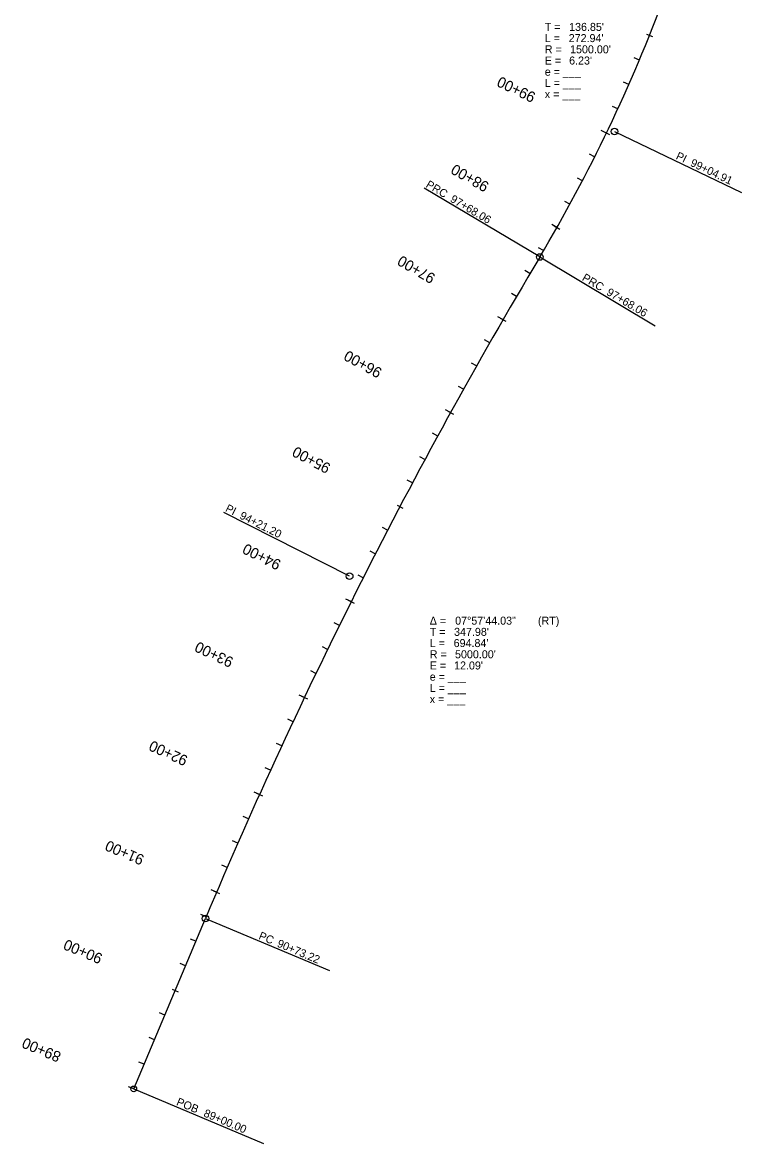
# Model space of a CAD drawing. Extents: x 14118486 to 14119897, y 8667783 to 8670021.
# Drawn here: x 14118486 to 14119160, y 8667783 to 8668833 of the extents above; entities that cross this region are included whole.
import ezdxf

# ---------------------------------------------------------------- set-up
doc = ezdxf.new("R2010")
doc.units = 0
for name, color, linetype in [('Alignment', 7, 'Continuous'), ('Draft_5', 7, 'Continuous'), ('TextAlignment', 7, 'Continuous'), ('TextAlignmentLrg', 7, 'Continuous'), ('TextAlignmentSml', 7, 'Continuous')]:
    doc.layers.add(name, color=color, linetype=linetype)

msp = doc.modelspace()

# ---------------------------------------------------------------- linework, layer by layer
at = {"layer": 'Alignment'}
msp.add_line((14118590.3, 8667833.8), (14118657.6, 8667993.5), dxfattribs=at)
for centre, radius, start, end in [((14117682.3, 8669381.1), 1500, 329.2012, 339.6267), ((14123265.6, 8666052.9), 5000, 149.2011, 157.1633)]:
    msp.add_arc(centre, radius, start, end, dxfattribs=at)
at = {"layer": 'Draft_5'}
msp.add_line((14118590.3, 8667833.8), (14118657.6, 8667993.5), dxfattribs=at)
for centre, radius, start, end in [((14117682.3, 8669381.1), 1500, 329.2012, 339.6267), ((14123265.6, 8666052.9), 5000, 149.2011, 157.1633)]:
    msp.add_arc(centre, radius, start, end, dxfattribs=at)
at = {"layer": 'TextAlignment'}
for p, q in [((14119040.9, 8668730.6), (14119159.9, 8668673.6)), ((14118970.8, 8668613.1), (14118862.6, 8668677.6)), ((14118862.6, 8668677.6), (14118862.6, 8668677.6)), ((14119159.9, 8668673.6), (14119159.9, 8668673.6)), ((14118970.8, 8668613.1), (14119079, 8668548.6)), ((14119079, 8668548.6), (14119079, 8668548.6)), ((14118792.6, 8668314.2), (14118674.8, 8668373.7)), ((14118674.8, 8668373.7), (14118674.8, 8668373.7)), ((14118657.6, 8667993.5), (14118773.7, 8667944.6)), ((14118773.7, 8667944.6), (14118773.7, 8667944.6)), ((14118590.3, 8667833.8), (14118712, 8667782.6)), ((14118712, 8667782.6), (14118712, 8667782.6))]:
    msp.add_line(p, q, dxfattribs=at)
for centre, radius in [((14119040.9, 8668730.6), 3.12), ((14118970.8, 8668613.1), 3.12), ((14118970.8, 8668613.1), 3.12), ((14118792.6, 8668314.2), 3.12), ((14118657.6, 8667993.5), 3.12), ((14118590.3, 8667833.8), 2.67)]:
    msp.add_circle(centre, radius, dxfattribs=at)
at = {"layer": 'TextAlignmentLrg'}
for p, q in [((14119070.9, 8668821.8), (14119076.5, 8668819.5)), ((14119033.3, 8668729.2), (14119028.4, 8668731.6)), ((14118986.8, 8668640.7), (14118982.1, 8668643.4)), ((14118936.3, 8668554.4), (14118931.6, 8668557.1)), ((14118887.2, 8668467.3), (14118882.4, 8668469.9)), ((14118837.1, 8668380.7), (14118842.5, 8668377.8)), ((14118794.1, 8668290.3), (14118789.2, 8668292.7)), ((14118750.3, 8668200.4), (14118745.3, 8668202.8)), ((14118708.2, 8668109.7), (14118703.3, 8668111.9)), ((14118668, 8668018.1), (14118663, 8668020.3)), ((14118626.3, 8667927.2), (14118632, 8667924.8)), ((14118590.3, 8667833.8), (14118585.3, 8667835.9))]:
    msp.add_line(p, q, dxfattribs=at)
at = {"layer": 'TextAlignmentSml'}
for p, q in [((14119070.9, 8668821.8), (14119076.5, 8668819.5)), ((14119064.2, 8668797.6), (14119059.1, 8668799.7)), ((14119054.2, 8668774.6), (14119049.3, 8668776.8)), ((14119043.9, 8668751.8), (14119039, 8668754.1)), ((14119030.5, 8668730.6), (14119036, 8668727.9)), ((14119022.2, 8668706.8), (14119017.3, 8668709.3)), ((14119010.8, 8668684.6), (14119006, 8668687.1)), ((14118999, 8668662.5), (14118994.2, 8668665.1)), ((14118984.2, 8668642.2), (14118989.5, 8668639.2)), ((14118974.3, 8668619.1), (14118969.6, 8668621.8)), ((14118961.6, 8668597.6), (14118956.9, 8668600.3)), ((14118948.9, 8668576), (14118944.2, 8668578.8)), ((14118933.7, 8668555.9), (14118939, 8668552.9)), ((14118923.9, 8668532.7), (14118919.1, 8668535.4)), ((14118911.5, 8668511), (14118906.8, 8668513.6)), ((14118899.3, 8668489.2), (14118894.5, 8668491.8)), ((14118884.5, 8668468.8), (14118889.9, 8668465.8)), ((14118875.2, 8668445.4), (14118870.4, 8668448)), ((14118863.2, 8668423.4), (14118858.4, 8668426)), ((14118851.5, 8668401.4), (14118846.6, 8668403.9)), ((14118837.1, 8668380.7), (14118842.5, 8668377.8)), ((14118828.2, 8668357.1), (14118823.3, 8668359.6)), ((14118816.7, 8668334.9), (14118811.9, 8668337.4)), ((14118805.4, 8668312.6), (14118800.5, 8668315.1)), ((14118791.4, 8668291.6), (14118796.9, 8668288.9)), ((14118783, 8668267.9), (14118778.1, 8668270.3)), ((14118772, 8668245.5), (14118767.1, 8668247.8)), ((14118761.1, 8668223), (14118756.2, 8668225.3)), ((14118747.5, 8668201.7), (14118753, 8668199.1)), ((14118739.6, 8668177.8), (14118734.7, 8668180.1)), ((14118729, 8668155.1), (14118724.1, 8668157.4)), ((14118718.6, 8668132.4), (14118713.6, 8668134.7)), ((14118705.4, 8668110.9), (14118711, 8668108.4)), ((14118698, 8668086.9), (14118693, 8668089.1)), ((14118687.9, 8668064), (14118682.9, 8668066.2)), ((14118677.9, 8668041.1), (14118672.9, 8668043.3)), ((14118665.2, 8668019.3), (14118670.8, 8668016.9)), ((14118658.2, 8667995.1), (14118653.2, 8667997.2)), ((14118648.5, 8667972.1), (14118643.5, 8667974.2)), ((14118638.8, 8667949), (14118633.8, 8667951.2)), ((14118626.3, 8667927.2), (14118632, 8667924.8)), ((14118619.4, 8667903), (14118614.4, 8667905.1)), ((14118609.7, 8667879.9), (14118604.7, 8667882)), ((14118600, 8667856.9), (14118595, 8667859)), ((14118587.5, 8667835), (14118593.1, 8667832.6))]:
    msp.add_line(p, q, dxfattribs=at)

# ---------------------------------------------------------------- texts
at = {"layer": 'TextAlignment'}
for s, p in [('T = ', (14118975.5, 8668824.9)), ("136.85'", (14118998.3, 8668824.9)), ('L = ', (14118975.5, 8668814.4)), ("272.94'", (14118997.9, 8668814.4)), ('R = ', (14118975.5, 8668803.9)), ("1500.00'", (14118999.2, 8668803.9)), ('E = ', (14118975.5, 8668793.4)), ("6.23'", (14118998.3, 8668793.4)), ('e = ___ ', (14118975.5, 8668782.9)), ('L = ___', (14118975.5, 8668772.4)), ('x = ___', (14118975.5, 8668761.9)), ('Δ = ', (14118867.7, 8668268.7)), ('07°57\'44.03"', (14118891.5, 8668268.7)), (' (RT)', (14118966.3, 8668268.7)), ('T = ', (14118867.7, 8668258.2)), ("347.98'", (14118890.5, 8668258.2)), ('L = ', (14118867.7, 8668247.7)), ("694.84'", (14118890.1, 8668247.7)), ('R = ', (14118867.7, 8668237.2)), ("5000.00'", (14118891.4, 8668237.2)), ('E = ', (14118867.7, 8668226.7)), ("12.09'", (14118890.5, 8668226.7)), ('e = ___ ', (14118867.7, 8668216.2)), ('L = ___', (14118867.7, 8668205.7)), ('x = ___', (14118867.7, 8668195.2))]:
    msp.add_text(s, height=7.5, dxfattribs=at).set_placement(p)
for s, rotation, p in [('PI ', 334.4139, (14119097.7, 8668705.2)), ('99+04.91', 334.4139, (14119111.2, 8668698.8)), ('PRC', 329.2012, (14118863.4, 8668679)), ('97+68.06', 329.2012, (14118886.2, 8668665.4)), ('PRC', 329.2011, (14119009.8, 8668591.7)), ('97+68.06', 329.2011, (14119032.7, 8668578.1)), ('PI ', 333.1822, (14118675.5, 8668375.2)), ('94+21.20', 333.1822, (14118688.9, 8668368.5)), ('PC', 337.1633, (14118706.8, 8667974.5)), ('90+73.22', 337.1633, (14118724, 8667967.3)), ('POB ', 337.1633, (14118629.7, 8667819)), ('89+00.00', 337.1633, (14118655.2, 8667808.3))]:
    msp.add_text(s, height=7.5, rotation=rotation, dxfattribs=at).set_placement(p)
at = {"layer": 'TextAlignmentLrg'}
for s, rotation, p in [('95+00', 152.2728, (14118775.7, 8668418.6)), ('90+00', 157.1633, (14118562, 8667959.7))]:
    msp.add_text(s, height=10.02, rotation=rotation, dxfattribs=at).set_placement(p)
at = {"layer": 'TextAlignmentSml'}
for s, rotation, p in [('99+00', 154.241, (14118967.9, 8668766.3)), ('98+00', 150.4213, (14118924.1, 8668682.1)), ('97+00', 149.981, (14118873.9, 8668596.2)), ('96+00', 151.1269, (14118823.9, 8668507.9)), ('95+00', 152.2728, (14118775.7, 8668418.6)), ('94+00', 153.4187, (14118729.3, 8668328.3)), ('93+00', 154.5646, (14118684.7, 8668237.1)), ('92+00', 155.7105, (14118641.9, 8668145.1)), ('91+00', 156.8565, (14118601, 8668052.2)), ('90+00', 157.1633, (14118562, 8667959.7)), ('89+00', 157.1633, (14118523.1, 8667867.6))]:
    msp.add_text(s, height=10.02, rotation=rotation, dxfattribs=at).set_placement(p)

doc.saveas('drawing.dxf')
